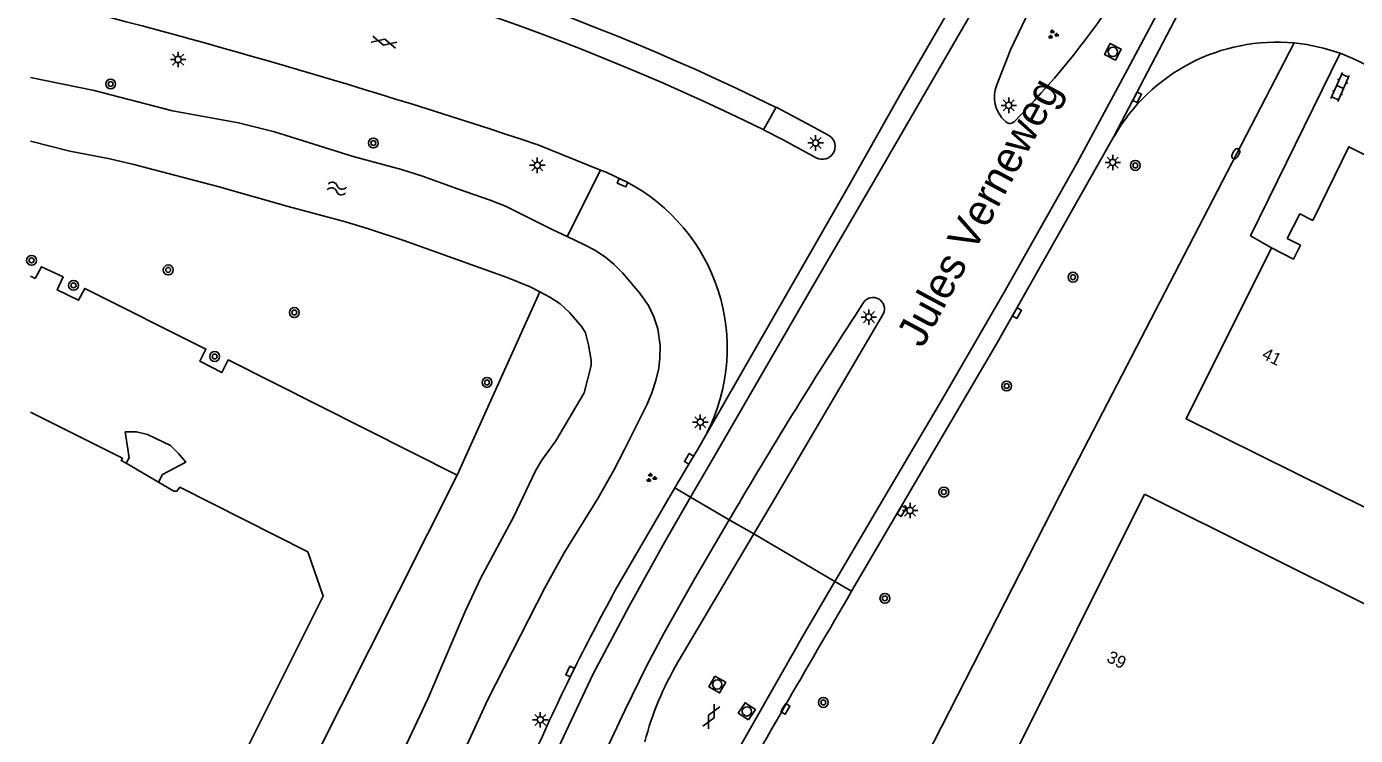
# Model space of a CAD drawing. Extents: x 135999 to 138000, y 396000 to 398501.
# Drawn here: x 135999.7 to 136106.9, y 397866.2 to 397923.4 of the extents above; entities that cross this region are included whole.
import ezdxf

# ---------------------------------------------------------------- set-up
doc = ezdxf.new("R2010")
doc.units = 0
for name, color, linetype in [('gg-anno-huisnummerreeks BGT', 7, 'Continuous'), ('gg-anno-openbare ruimte label', 7, 'Continuous'), ('gg-bbg-hoofdgebouw', 7, 'Continuous'), ('gg-knt-trap', 7, 'Continuous'), ('gg-knt-verharding', 7, 'Continuous'), ('gg-knt-verharding nz', 7, 'Continuous'), ('gg-kntw-bovenkant insteek waterloop', 7, 'Continuous'), ('gt-grn-groengrens', 7, 'Continuous'), ('gt-grn-weggrens', 7, 'Continuous'), ('gt-symb-boom', 7, 'Continuous'), ('gt-symb-brandkraan', 7, 'Continuous'), ('gt-symb-gesloten verharding', 7, 'Continuous'), ('gt-symb-groenvak', 7, 'Continuous'), ('gt-symb-klinker verharding', 7, 'Continuous'), ('gt-symb-kolk', 7, 'Continuous'), ('gt-symb-lichtmast', 7, 'Continuous'), ('gt-symb-rioolschacht', 7, 'Continuous'), ('gt-symb-watersymbool', 7, 'Continuous')]:
    doc.layers.add(name, color=color, linetype=linetype)

# ---------------------------------------------------------------- blocks, each defined once
blk = doc.blocks.new('gt0-KL1')
at = {"layer": 'gt-symb-klinker verharding'}
for p, q in [((-1.15, 0.3), (1.15, 0.3)), ((-1, -0.3), (-1, 0.3)), ((-0.5, 0.3), (-0.5, 0.45)), ((0, -0.3), (0, 0.3)), ((0.5, 0.3), (0.5, 0.45)), ((1, -0.3), (1, 0.3)), ((-1.15, -0.3), (1.15, -0.3)), ((-0.5, -0.45), (-0.5, -0.3)), ((0.5, -0.45), (0.5, -0.3))]:
    blk.add_line(p, q, dxfattribs=at)
blk = doc.blocks.new('gt0-BR')
at = {"layer": 'gt-symb-brandkraan'}
for centre, radius, start, end in [((-0.24, 0), 0.206, 107.5669, 252.4331), ((0.6, -2.66), 3, 106.892, 107.5669), ((0, -0.69), 0.938, 73.108, 106.892), ((-0.6, -2.66), 3, 72.4331, 73.108), ((0.24, 0), 0.206, 287.567, 72.4331), ((0.6, 2.66), 3, 252.4331, 253.108), ((0, 0.69), 0.938, 253.108, 286.8921), ((-0.6, 2.66), 3, 286.8921, 287.567)]:
    blk.add_arc(centre, radius, start, end, dxfattribs=at)
blk = doc.blocks.new('gt0-LMAST')
at = {"layer": 'gt-symb-lichtmast'}
for p, q in [((-0.18, 0.17), (-0.45, 0.44)), ((-0.01, 0.25), (-0.01, 0.62)), ((0.17, 0.17), (0.44, 0.44)), ((-0.26, 0), (-0.63, 0)), ((-0.18, -0.18), (-0.45, -0.45)), ((-0.01, -0.25), (-0.01, -0.63)), ((0.44, -0.45), (0.17, -0.18)), ((0.24, 0), (0.62, 0))]:
    blk.add_line(p, q, dxfattribs=at)
blk.add_circle((-0.01, 0), 0.25, dxfattribs=at)
blk = doc.blocks.new('gt0-KOLK')
at = {"layer": 'gt-symb-kolk'}
blk.add_lwpolyline([(0, 0), (0.38, 0), (0.38, 0.4), (-0.38, 0.4), (-0.38, 0), (0, 0)], dxfattribs=at)
blk = doc.blocks.new('gt0-RS')
at = {"layer": 'gt-symb-rioolschacht'}
blk.add_lwpolyline([(-0.5, -0.5), (0.5, -0.5), (0.5, 0.5), (-0.5, 0.5)], close=True, dxfattribs=at)
blk.add_circle((0, 0), 0.375, dxfattribs=at)
blk = doc.blocks.new('gt0-GRVAK')
at = {"layer": 'gt-symb-groenvak'}
for p, q in [((-0.11, 0.19), (-0.23, 0.24)), ((-0.18, 0.15), (0.09, 0.15)), ((-0.09, 0.21), (-0.16, 0.32)), ((-0.05, 0.21), (-0.05, 0.39)), ((0, 0.21), (0.06, 0.32)), ((0.02, 0.19), (0.13, 0.24)), ((0.26, -0.05), (0.2, 0.06)), ((0.3, -0.05), (0.3, 0.13)), ((0.35, -0.05), (0.41, 0.06)), ((-0.24, -0.23), (-0.36, -0.18)), ((-0.32, -0.26), (-0.05, -0.26)), ((-0.23, -0.21), (-0.29, -0.1)), ((-0.18, -0.2), (-0.18, -0.02)), ((-0.14, -0.21), (-0.07, -0.1)), ((-0.12, -0.23), (0, -0.18)), ((0.24, -0.07), (0.12, -0.02)), ((0.17, -0.11), (0.44, -0.11)), ((0.37, -0.07), (0.49, -0.02))]:
    blk.add_line(p, q, dxfattribs=at)
blk = doc.blocks.new('gt0-BOOM')
at = {"layer": 'gt-symb-boom'}
for radius in [0.4, 0.2]:
    blk.add_circle((0, 0), radius, dxfattribs=at)
blk = doc.blocks.new('gt0-GESVH1')
at = {"layer": 'gt-symb-gesloten verharding'}
for p, q in [((-0.99, -0.26), (0.01, 0.24)), ((0.01, -0.26), (-0.99, 0.24)), ((0.01, 0.24), (1.01, -0.26)), ((1.01, 0.24), (0.01, -0.26))]:
    blk.add_line(p, q, dxfattribs=at)
blk = doc.blocks.new('gt0-WA')
at = {"layer": 'gt-symb-watersymbool'}
for centre, start, end in [((-0.32, 0.02), 28.0725, 151.9275), ((0.43, 0.42), 208.0725, 331.9275), ((-0.32, -0.43), 28.0725, 151.9275), ((0.43, -0.03), 208.0725, 331.9275)]:
    blk.add_arc(centre, 0.425, start, end, dxfattribs=at)

msp = doc.modelspace()

# ---------------------------------------------------------------- linework, layer by layer
at = {"layer": 'gg-bbg-hoofdgebouw'}
for p, q in [((136000, 397892.31), (136007.42, 397888.59)), ((136007.73, 397888.17), (136010.34, 397886.64)), ((136078.33, 397862.45), (136089.92, 397885.69))]:
    msp.add_line(p, q, dxfattribs=at)
for points in [[(136138.87, 397898.77), (136138.38, 397897.79), (136106.42, 397913.72), (136103.52, 397907.77)], [(136103.52, 397907.77), (136102.46, 397908.3), (136101.45, 397906.32), (136102.51, 397905.77), (136101.94, 397904.65), (136100.16, 397905.56)], [(136100.16, 397905.56), (136093.28, 397891.77), (136122.6, 397877.24)], [(136007.42, 397888.59), (136007.32, 397888.4), (136007.73, 397888.17)], [(136010.34, 397886.64), (136011.58, 397885.91), (136011.83, 397885.91), (136012.05, 397886.24), (136022.4, 397881.03)], [(136089.92, 397885.69), (136117.76, 397871.8), (136106.17, 397848.57), (136099.46, 397851.91)], [(136022.4, 397881.03), (136023.62, 397877.45), (136002.66, 397835.52), (136000, 397834.66)]]:
    msp.add_lwpolyline(points, dxfattribs=at)
at = {"layer": 'gg-knt-trap'}
msp.add_lwpolyline([(136007.73, 397888.17), (136007.97, 397888.61), (136007.66, 397890.7), (136008.57, 397890.7), (136009.45, 397890.5), (136011.32, 397889.6), (136011.96, 397888.96), (136012.54, 397888.27), (136010.66, 397887.27), (136010.34, 397886.64)], dxfattribs=at)
at = {"layer": 'gg-knt-verharding'}
for p, q in [((136046.02, 397911.84), (136040.89, 397913.9)), ((136000, 397903.27), (136000.37, 397903.08)), ((136059.81, 397884.87), (136068.86, 397900.25)), ((136053.83, 397889.27), (136054.61, 397890.64)), ((136053.41, 397888.57), (136053.83, 397889.27)), ((136052.02, 397886.19), (136053.41, 397888.57)), ((136034.44, 397887.21), (136003.65, 397826.01)), ((136047.18, 397877.87), (136052.02, 397886.19)), ((136057.17, 397884.92), (136056.41, 397883.62)), ((136058.38, 397882.47), (136059.81, 397884.87)), ((136052.26, 397872.11), (136058.38, 397882.47))]:
    msp.add_line(p, q, dxfattribs=at)
for points in [[(136104.03, 397945.52), (136098.71, 397936.11), (136087.46, 397914.54)], [(136081.25, 397926.05), (136079.1, 397921.54), (136078, 397918.71)], [(136105.72, 397921.26), (136104.38, 397921.68), (136103, 397921.97), (136102.01, 397922.1)], [(136105.72, 397921.26), (136098.49, 397906.54), (136100.16, 397905.56)], [(136109.43, 397919.56), (136106.74, 397920.85), (136105.72, 397921.26)], [(136060.19, 397916.9), (136062.67, 397915.6), (136064.49, 397914.61)], [(136063.43, 397912.83), (136060.76, 397914.28), (136059.18, 397915.08)], [(136087.46, 397914.54), (136078.04, 397897.89), (136066.28, 397877.84)], [(136048.07, 397910.91), (136047.87, 397911), (136046.47, 397911.66), (136046.02, 397911.84)], [(136000.37, 397903.08), (136000.9, 397904.03), (136002.63, 397903.21), (136002.16, 397902.17), (136003.87, 397901.33), (136004.39, 397902.29), (136014.17, 397897.39), (136013.68, 397896.41), (136015.46, 397895.5), (136015.97, 397896.51), (136034.44, 397887.21)], [(136056.41, 397883.62), (136053.63, 397878.87), (136051.15, 397874.49), (136049.74, 397871.81), (136047.98, 397868.22), (136045.43, 397862.78), (136043.81, 397859.11), (136042.26, 397855.4)]]:
    msp.add_lwpolyline(points, dxfattribs=at)
for centre, radius, start, end in [((135973.7, 397741.02), 195.99, 63.8131, 80.5683), ((135974.1, 397742.38), 192.53, 63.7721, 80.6335), ((135868.06, 397396.3), 545.69, 71.5361, 76.0083), ((136031.65, 397962.93), 67.14, 315.3209, 326.2715), ((136100.58, 397907.07), 15.09, 84.5519, 150.3506), ((136080.35, 397917.71), 2.55, 157.0243, 228.5707), ((136079.06, 397916.09), 0.492, 215.5778, 312.241), ((136063.91, 397913.74), 1.04, 242.0843, 56.4614), ((136041.11, 397897.47), 15.13, 333.1511, 62.6286), ((136397.94, 397684.62), 395.27, 146.7861, 149.5543), ((136068.01, 397900.62), 0.927, 336.2556, 146.1472), ((136195.39, 397796.36), 169.14, 151.1916, 156.2607), ((137072.17, 397287.13), 1166.51, 149.57642, 150.64507), ((136073.16, 397859.67), 24.32, 149.2333, 165.6639)]:
    msp.add_arc(centre, radius, start, end, dxfattribs=at)
at = {"layer": 'gg-knt-verharding nz'}
for p, q in [((136059.18, 397915.08), (136060.19, 397916.9)), ((136056.41, 397883.62), (136058.38, 397882.47))]:
    msp.add_line(p, q, dxfattribs=at)
for points in [[(136133.66, 398020.2), (136129.13, 398011.58), (136124.53, 398002.86), (136120.77, 397995.74), (136116.04, 397986.8), (136112.34, 397979.91), (136110.3, 397976.61), (136108.04, 397973.29), (136103.39, 397966.89), (136098.64, 397960.43), (136095.04, 397955.63), (136091.5, 397950.64), (136088.18, 397945.61), (136085.13, 397940.41), (136081.14, 397933.52), (136074.17, 397921.46), (136068.17, 397911.11), (136063.18, 397902.51), (136055.15, 397888.66), (136053.29, 397885.45)], [(136064.93, 397878.63), (136068.53, 397884.76), (136073.62, 397893.38), (136078.57, 397901.93), (136084.5, 397912.43), (136088.33, 397919.55), (136095.89, 397933.74), (136101.55, 397944.31), (136109.04, 397958.4), (136117.47, 397974.24), (136123.12, 397984.88), (136131.17, 398000.05), (136140.42, 398017.6)], [(136076.97, 397929.66), (136070.28, 397918.08), (136066.22, 397910.86), (136054.61, 397890.64)], [(136053.29, 397885.45), (136051.2, 397881.83), (136048.32, 397876.65), (136045.43, 397871.17), (136042.8, 397865.65), (136040.38, 397860.09), (136037.36, 397852.55), (136034.03, 397842.97), (136031.23, 397835.11), (136029.11, 397829.72), (136026.95, 397825.22)], [(136045.61, 397843.09), (136046.4, 397845.82), (136047.94, 397848.67), (136049.87, 397852.17), (136053.82, 397859.26), (136057.8, 397866.24), (136062.45, 397874.42), (136064.93, 397878.63)]]:
    msp.add_lwpolyline(points, dxfattribs=at)
at = {"layer": 'gg-kntw-bovenkant insteek waterloop'}
msp.add_line((136000, 397914.17), (136003.17, 397913.37), dxfattribs=at)
for points in [[(136000, 397919.32), (136005.14, 397918.25), (136011.46, 397916.61), (136016.79, 397915.64), (136019.7, 397914.91), (136026.04, 397912.92), (136029.96, 397911.88), (136031.64, 397911.35), (136034.46, 397910.32), (136037.12, 397909.41), (136038.34, 397908.91), (136042.11, 397907.04), (136043.32, 397906.47)], [(136003.17, 397913.37), (136006.41, 397912.74), (136008.36, 397912.29), (136015.12, 397910.51), (136020.81, 397908.89), (136025.44, 397907.65), (136027.29, 397907.1), (136030.14, 397906.15), (136038.49, 397903.16), (136040.34, 397902.4), (136041.11, 397902.01)], [(136034.96, 397864.83), (136036.91, 397869.12), (136041.51, 397878.13), (136043.09, 397880.94), (136045.79, 397885.33), (136047.07, 397887.55), (136047.99, 397889.33), (136049.79, 397892.93), (136050.17, 397893.86), (136050.49, 397894.86), (136050.71, 397895.85), (136050.8, 397896.68), (136050.82, 397897.68), (136050.63, 397899.03), (136050.33, 397899.99), (136049.89, 397900.9), (136049.17, 397901.93), (136047.78, 397903.53), (136047.08, 397904.25), (136046.44, 397904.79), (136045.61, 397905.34), (136044.73, 397905.81), (136043.32, 397906.47)], [(136041.11, 397902.01), (136041.93, 397901.59), (136042.75, 397901.03), (136043.51, 397900.35), (136044.52, 397899.19), (136044.79, 397898.7), (136045.04, 397897.73), (136045.25, 397896.49), (136045.25, 397896.06), (136044.69, 397893.86), (136042.41, 397889.98), (136041.29, 397888.41), (136040.78, 397887.55), (136039.02, 397883.88), (136036.35, 397878.93), (136035.08, 397876.22), (136032.08, 397869.15), (136028.61, 397861.8)]]:
    msp.add_lwpolyline(points, dxfattribs=at)
at = {"layer": 'gt-grn-groengrens'}
for p, q in [((136046.02, 397911.84), (136043.32, 397906.47)), ((136041.11, 397902.01), (136034.44, 397887.21))]:
    msp.add_line(p, q, dxfattribs=at)
msp.add_lwpolyline([(136050.77, 397822.97), (136056.36, 397833.3), (136083.08, 397885.6), (136102.01, 397922.1)], dxfattribs=at)
at = {"layer": 'gt-grn-weggrens'}
for p, q in [((136053.29, 397885.45), (136052.02, 397886.19)), ((136056.41, 397883.62), (136053.29, 397885.45)), ((136058.38, 397882.47), (136064.93, 397878.63)), ((136064.93, 397878.63), (136066.28, 397877.84))]:
    msp.add_line(p, q, dxfattribs=at)

# ---------------------------------------------------------------- block references
at = {"layer": 'gt-symb-boom'}
for p in [(136006.48, 397918.78), (136027.68, 397914.02), (136089.18, 397912.21), (136000.09, 397904.55), (136011.12, 397903.78), (136084.15, 397903.19), (136003.48, 397902.53), (136021.3, 397900.34), (136014.87, 397896.79), (136036.85, 397894.7), (136078.8, 397894.41), (136073.73, 397885.85), (136068.97, 397877.27), (136064, 397868.87)]:
    msp.add_blockref('gt0-BOOM', p, dxfattribs=at)
at = {"layer": 'gt-symb-brandkraan', "rotation": 60.717171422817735}
msp.add_blockref('gt0-BR', (136097.29, 397913.15), dxfattribs=at)
at = {"layer": 'gt-symb-gesloten verharding'}
for p, rotation in [((136028.54, 397922.16), -13.88341803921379), ((136054.95, 397867.73), 62.743128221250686)]:
    msp.add_blockref('gt0-GESVH1', p, dxfattribs=dict(at, rotation=rotation))
at = {"layer": 'gt-symb-groenvak'}
for p in [(136082.53, 397922.78), (136050.09, 397887)]:
    msp.add_blockref('gt0-GRVAK', p, dxfattribs=at)
at = {"layer": 'gt-symb-klinker verharding', "rotation": -114.07883723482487}
msp.add_blockref('gt0-KL1', (136105.71, 397918.54), dxfattribs=at)
at = {"layer": 'gt-symb-kolk'}
for p, rotation in [((136089.16, 397917.8), -117.71850162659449), ((136047.87, 397911), 156.48544332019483), ((136079.45, 397900.39), -119.53878225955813), ((136053.33, 397888.43), 59.12897068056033), ((136070.14, 397884.42), -120.33480582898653), ((136043.74, 397871.27), 63.71668708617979), ((136060.77, 397868.45), -120.12860023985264)]:
    msp.add_blockref('gt0-KOLK', p, dxfattribs=dict(at, rotation=rotation))
at = {"layer": 'gt-symb-lichtmast'}
for p in [(136011.93, 397920.76), (136078.97, 397917.06), (136063.38, 397914.03), (136040.92, 397912.22), (136087.37, 397912.45), (136067.68, 397899.97), (136054.08, 397891.49), (136071.01, 397884.36), (136041.16, 397867.47)]:
    msp.add_blockref('gt0-LMAST', p, dxfattribs=at)
at = {"layer": 'gt-symb-rioolschacht'}
for p, rotation in [((136087.37, 397921.38), 63.33249782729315), ((136055.44, 397870.32), -119.74488129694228), ((136057.83, 397868.15), 56.62779761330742)]:
    msp.add_blockref('gt0-RS', p, dxfattribs=dict(at, rotation=rotation))
at = {"layer": 'gt-symb-watersymbool', "rotation": -9.321060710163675}
msp.add_blockref('gt0-WA', (136024.68, 397910.36), dxfattribs=at)

# ---------------------------------------------------------------- texts
at = {"layer": 'gg-anno-huisnummerreeks BGT'}
for s, p in [('41', (136099.32, 397896.67)), ('39', (136086.79, 397872.2))]:
    msp.add_text(s, height=1, rotation=333.5, dxfattribs=at).set_placement(p)
at = {"layer": 'gg-anno-openbare ruimte label'}
msp.add_text('Jules Verneweg', height=2.5, rotation=61.8, dxfattribs=at).set_placement((136072, 397897.4))

doc.saveas('drawing.dxf')
